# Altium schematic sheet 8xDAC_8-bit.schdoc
size 420 x 297 mm; Symbol: Drawing-Symbol_A4; @Project Name: Inverted_MAML_6x6; @Page Count: 1; @Update Date: 2026-06-15; @Create Date: 2026-06-15; @Schematic Name: Schematic1; @Page No: 1; @Page Name: P1; Company: EasyEDA.com; Version: V1.0; Page Size: A4; Device: Drawing-Symbol_A4; @Create Time: 21:23:07; @Update Time: 21:23:07; Border: 1; Width: 1655; Height: 1170; Region Start: 1; X Region Count: 6; Y Region Count: 4; Blade Width: 10; Title Block Position: 3
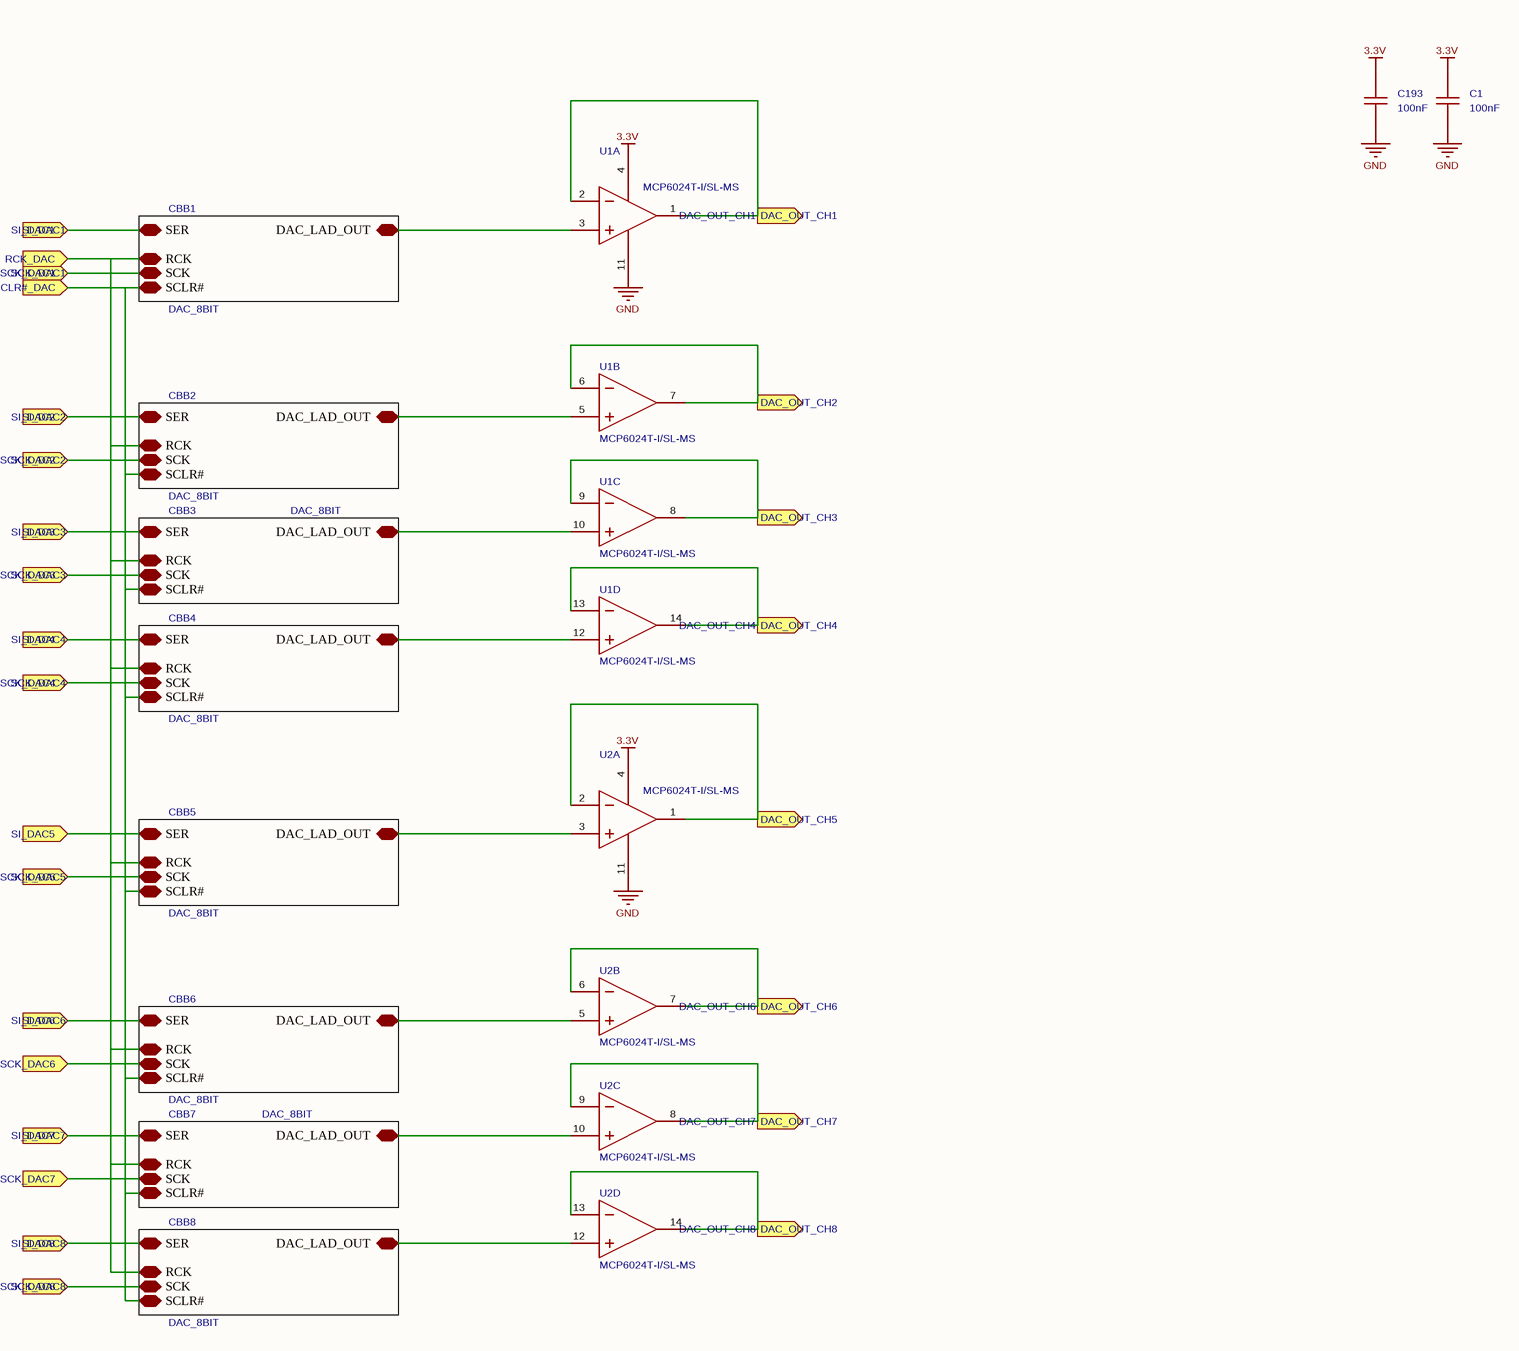
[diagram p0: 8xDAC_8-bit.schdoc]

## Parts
C1  100nF  [C0402]
C193  100nF  [C0402]
U1  MCP6024T-I/SL-MS  [SOIC-14_L8.7-W3.9-P1.27-LS6.0-BL-1]  (parts A,B,C,D of 4)
U2  MCP6024T-I/SL-MS  [SOIC-14_L8.7-W3.9-P1.27-LS6.0-BL-1]  (parts A,B,C,D of 4)

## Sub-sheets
CBB1 = DAC_8B_R_2R.schdoc: SER, RCK, SCK, SCLR#, DAC_LAD_OUT  | Symbol: DAC_8BIT
CBB2 = DAC_8B_R_2R.schdoc: SER, RCK, SCK, SCLR#, DAC_LAD_OUT  | Symbol: DAC_8BIT
CBB3 = DAC_8B_R_2R.schdoc: SER, RCK, SCK, SCLR#, DAC_LAD_OUT  | Symbol: DAC_8BIT
CBB4 = DAC_8B_R_2R.schdoc: SER, RCK, SCK, SCLR#, DAC_LAD_OUT  | Symbol: DAC_8BIT
CBB5 = DAC_8B_R_2R.schdoc: SER, RCK, SCK, SCLR#, DAC_LAD_OUT  | Symbol: DAC_8BIT
CBB6 = DAC_8B_R_2R.schdoc: SER, RCK, SCK, SCLR#, DAC_LAD_OUT  | Symbol: DAC_8BIT
CBB7 = DAC_8B_R_2R.schdoc: SER, RCK, SCK, SCLR#, DAC_LAD_OUT  | Symbol: DAC_8BIT
CBB8 = DAC_8B_R_2R.schdoc: SER, RCK, SCK, SCLR#, DAC_LAD_OUT  | Symbol: DAC_8BIT

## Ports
DAC_OUT_CH1 (out), DAC_OUT_CH2 (out), DAC_OUT_CH3 (out), DAC_OUT_CH4 (out), DAC_OUT_CH5 (out), DAC_OUT_CH6 (out), DAC_OUT_CH7 (out), DAC_OUT_CH8 (out), RCK_DAC (in), SCK_DAC1 (in), SCK_DAC2 (in), SCK_DAC3 (in), SCK_DAC4 (in), SCK_DAC5 (in), SCK_DAC6 (in), SCK_DAC7 (in), SCK_DAC8 (in), SCLR#_DAC (in), SI_DAC1 (in), SI_DAC2 (in), SI_DAC3 (in), SI_DAC4 (in), SI_DAC5 (in), SI_DAC6 (in), SI_DAC7 (in), SI_DAC8 (in)

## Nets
3.3V: C1.2 C193.2 U1.4(V+) U2.4(V+)
GND: C1.1 C193.1 U1.11(V-) U2.11(V-)
DAC_OUT_CH1: U1.1(OUT1) U1.2(IN1-) ; port DAC_OUT_CH1
DAC_OUT_CH2: U1.6(IN2-) U1.7(OUT2) ; port DAC_OUT_CH2
DAC_OUT_CH3: U1.8(OUT3) U1.9(IN3-) ; port DAC_OUT_CH3
DAC_OUT_CH4: U1.13(IN4-) U1.14(OUT4) ; port DAC_OUT_CH4
DAC_OUT_CH5: U2.1(OUT1) U2.2(IN1-) ; port DAC_OUT_CH5
DAC_OUT_CH6: U2.6(IN2-) U2.7(OUT2) ; port DAC_OUT_CH6
DAC_OUT_CH7: U2.8(OUT3) U2.9(IN3-) ; port DAC_OUT_CH7
DAC_OUT_CH8: U2.13(IN4-) U2.14(OUT4) ; port DAC_OUT_CH8
RCK_DAC: port RCK_DAC, sheet CBB1/RCK, sheet CBB2/RCK, sheet CBB3/RCK, sheet CBB4/RCK, sheet CBB5/RCK, sheet CBB6/RCK, sheet CBB7/RCK, sheet CBB8/RCK
SCK_DAC1: port SCK_DAC1, sheet CBB1/SCK
SCK_DAC2: port SCK_DAC2, sheet CBB2/SCK
SCK_DAC3: port SCK_DAC3, sheet CBB3/SCK
SCK_DAC4: port SCK_DAC4, sheet CBB4/SCK
SCK_DAC5: port SCK_DAC5, sheet CBB5/SCK
SCK_DAC6: port SCK_DAC6, sheet CBB6/SCK
SCK_DAC7: port SCK_DAC7, sheet CBB7/SCK
SCK_DAC8: port SCK_DAC8, sheet CBB8/SCK
SCLR#_DAC: port SCLR#_DAC, sheet CBB1/SCLR#, sheet CBB2/SCLR#, sheet CBB3/SCLR#, sheet CBB4/SCLR#, sheet CBB5/SCLR#, sheet CBB6/SCLR#, sheet CBB7/SCLR#, sheet CBB8/SCLR#
SI_DAC1: port SI_DAC1, sheet CBB1/SER
SI_DAC2: port SI_DAC2, sheet CBB2/SER
SI_DAC3: port SI_DAC3, sheet CBB3/SER
SI_DAC4: port SI_DAC4, sheet CBB4/SER
SI_DAC5: port SI_DAC5, sheet CBB5/SER
SI_DAC6: port SI_DAC6, sheet CBB6/SER
SI_DAC7: port SI_DAC7, sheet CBB7/SER
SI_DAC8: port SI_DAC8, sheet CBB8/SER
NetU1_3: U1.3(IN1+) ; sheet CBB1/DAC_LAD_OUT
NetU1_5: U1.5(IN2+) ; sheet CBB2/DAC_LAD_OUT
NetU1_10: U1.10(IN3+) ; sheet CBB3/DAC_LAD_OUT
NetU1_12: U1.12(IN4+) ; sheet CBB4/DAC_LAD_OUT
NetU2_3: U2.3(IN1+) ; sheet CBB5/DAC_LAD_OUT
NetU2_5: U2.5(IN2+) ; sheet CBB6/DAC_LAD_OUT
NetU2_10: U2.10(IN3+) ; sheet CBB7/DAC_LAD_OUT
NetU2_12: U2.12(IN4+) ; sheet CBB8/DAC_LAD_OUT

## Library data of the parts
C1 C193 = CL05B104KO5NNNC: Capacitance:100nF Tolerance:±10% Tolerance:±10% Voltage Rating:16V Temperature Coefficient:X7R; Manufacturer: SAMSUNG(三星); 3D Model: b7d13df3e9464d7a99d0651d1a5b4d570819f05c4eef4c71ace90d822a990e87; 3D Model Transform: 39.37,19.685,0,0,0,0,0,0,0; Tolerance: ±10%; Voltage Rating: 16V; Temperature Coefficient: X7R; AddInBom: yes; ModelName: C0402_L1.0-W0.5-H0.5
U1 U2 = MCP6024T-I/SL-MS: Manufacturer: MSKSEMI(美森科); Relevance: []; AddInBom: yes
